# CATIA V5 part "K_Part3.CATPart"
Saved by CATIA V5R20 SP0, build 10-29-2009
Part number: poignee
Publications: "Corps principal", "ecart entre les barres de la poignée", "hauteur barres poignée", "Point.1", "Point.2", "Point.3", "Point.4", "Droite.1", "Droite.2", "Droite.3", "Droite.4"
Bounding box of the stored display mesh (mm): x -50 to -50, y -25 to 25, z 1000 to 1400
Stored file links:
  G:\Khaled_CFAO_2011\ST2M\ST2M_GR1\cdurantin\cdurantin\Khaled\CAD_ThinkMOTION\K_Part3.CATPart
  G:\Khaled_CFAO_2011\ST2M\ST2M_GR1\cdurantin\cdurantin\Khaled\CAD_ThinkMOTION\K_Part2.CATPart
  G:\Khaled_CFAO_2011\ST2M\ST2M_GR1\cdurantin\cdurantin\Khaled\CAD_ThinkMOTION\K_Corps.CATPart
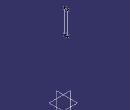
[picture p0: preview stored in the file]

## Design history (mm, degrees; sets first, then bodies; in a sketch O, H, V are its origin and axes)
Parameters
  `ecart entre les barres de la poignée` = 50 mm
  `hauteur barres poignée` = 400 mm
External parameters (linked from other documents)
  `External.hauteur des barres` = 1000 mm
  `External.Ecart entre les barres du corps` = 100 mm
Body1 (main body)
  Point1: (-50 {= -`External.Ecart entre les barres du corps` /2}, 25 {= `ecart entre les barres de la poignée` /2}, 1000 {= `External.hauteur des barres`})
  Point2: (-50 {= -`External.Ecart entre les barres du corps` /2}, -25 {= -`ecart entre les barres de la poignée` /2}, 1000 {= `External.hauteur des barres`})
  Point3: (-50 {= -`External.Ecart entre les barres du corps` /2}, 25 {= `ecart entre les barres de la poignée` /2}, 1400 {= `External.hauteur des barres` +`hauteur barres poignée`})
  Point4: (-50 {= -`External.Ecart entre les barres du corps` /2}, -25 {= -`ecart entre les barres de la poignée` /2}, 1400 {= `External.hauteur des barres` +`hauteur barres poignée`})
  Line1: type PtPt, FirstPoint Point1, SecondPoint Point2
  Line2: type PtPt, FirstPoint Point3, SecondPoint Point1
  Line3: type PtPt, FirstPoint Point4, SecondPoint Point2
  Line4: type PtPt, FirstPoint Point3, SecondPoint Point4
